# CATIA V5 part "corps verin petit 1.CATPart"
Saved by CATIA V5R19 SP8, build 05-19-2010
Part number: corps verin petit 1
Bounding box of the stored display mesh (mm): x -6.642 to 19.911, y 48 to 54, z 98.028 to 139.838
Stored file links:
  G:\EU_thinkMotion\CFAO_2010\MMS_groupe1\MMS_groupe1\A reprendre\OK\glenerrant\glenerrant\glenerrant\corps verin petit 1.CATPart
  C:\Users\Gauthier\Documents\IFMA\Projet CFAO\Systeme.CATProduct
  G:\EU_thinkMotion\CFAO_2010\MMS_groupe1\MMS_groupe1\A reprendre\OK\glenerrant\glenerrant\glenerrant\corps verin2.CATPart
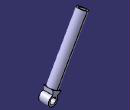
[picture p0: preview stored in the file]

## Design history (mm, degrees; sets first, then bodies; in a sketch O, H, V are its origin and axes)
Set1
  Plane1: linked copy from another document
Set2
  Point1: (-9, 51, 147)
  Point2: (17, 51, 101)
  Point3: (17, -51, 101)
  Line1: type PtPt, FirstPoint Point1, SecondPoint Point2
  Line2: type PtPt, FirstPoint Point2, SecondPoint Point3
  Plane2: type Normal, Curve Line1, RefPoint Point2
Body1 (main body)
  Sketch1 on Plane1, origin (0, 51, 0), H (1, 0, 0), V (0, 0, 1)
    circle A1 centre (17, 101) radius 2
    point P1 (17, 101)
    reference projected point E1 (17, 101) from Point2
    arc A2 centre (17, 101) radius 3 from (14.3905, 102.48) to (17.0779, 103.999) ccw
    point P2 (17, 101)
    reference projected point E2 (17, 101) from Point2
    line L1 (17.0779, 103.999) -> (17.1514, 106.829)
    point P4 (17.1514, 106.829)
    line L2 (14.3905, 102.48) -> (11.928, 103.8766)
    line L3 (17.1514, 106.829) -> (11.928, 103.8766)
    reference intersected line E3 through (-39.149, 69.2636) direction (0.8706, 0.4921) from Plane2
    reference intersected line E4 through (-39.149, 69.2636) direction (0.8706, 0.4921) from Plane2
    reference projected point E5 (17, 101) from Point2
    reference projected point E6 (17, 101) from Point2
    reference projected line E7 (-9, 147) -> (17, 101) from Line1
    radius A1 = 2
    radius A2 = 3
    distance L3 E4 = 5
    length L3 = 6
    distance P4 E7 = 3
    coincidence: P1 E1, P2 E2, L1 E5, L2 E6
    parallelism: L3 E3
  Pad1: profile Sketch1, direction (0, -1, 0), length 3, opposite side length 3
  Sketch2 on Plane2, origin (-39.149, 0, 69.2636), H (0, 1, 0), V (0.8706, 0, 0.4921)
    circle A1 centre (51, 64.4974) radius 3
    point P1 (51, 64.4974)
    reference projected point E1 (51, 64.4974) from Point2
    circle A2 centre (51, 64.4974) radius 2
    point P2 (51, 64.4974)
    reference projected point E2 (51, 64.4974) from Point2
    radius A1 = 3
    radius A2 = 2
    coincidence: E1 P1, P2 E2
  Pad2: profile Sketch2, direction (-0.4921, 0, 0.8706), length 43, opposite side length -5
